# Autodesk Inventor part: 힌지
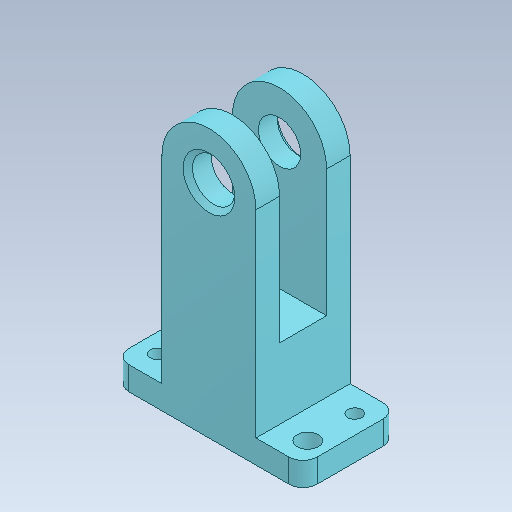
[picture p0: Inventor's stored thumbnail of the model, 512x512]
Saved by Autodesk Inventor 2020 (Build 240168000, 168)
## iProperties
Created: 2024-04
Part Number: 힌지
Material: 알루미늄 6061
Document SubType Name: Modeling
Designer: oem
Density: 2.71 g/cm^3
Appearance: 기본값
Mass: 43.4573 g
Surface Area: 69.4275 cm^2
Volume: 16.0359 cm^3
Sending System: Autodesk Inventor 2025
Preprocessor: ST-DEVELOPER v20
Author: jhkim
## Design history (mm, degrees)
feature "솔리드1"
node "솔리드2"
